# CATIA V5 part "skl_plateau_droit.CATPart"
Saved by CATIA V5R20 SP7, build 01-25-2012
Part number: skl_plateau_droit
Publications: "Point.F", "Point.G", "Droite.1", "Droite.2", "Droite.3"
Bounding box of the stored display mesh (mm): x 150 to 150, y 0 to 30, z 0 to 20
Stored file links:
  D:\IFMA\COURS\2A\projet balance IAO\catia\skl_plateau_droit.CATPart
  D:\IFMA\COURS\2A\projet balance IAO\catia\Skl_projet_balance.CATProduct
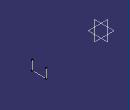
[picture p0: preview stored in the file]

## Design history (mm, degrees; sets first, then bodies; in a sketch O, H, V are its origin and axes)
Set1
  Point1 "Point.F": linked copy from another document
  Point2 "Point.G": linked copy from another document
  Plane1 "Plan_plateau_droit": linked copy from another document
Body1 (main body)
  Point3 "Point.F": stored without definition
  Point4 "Point.G": stored without definition
  Line1: type PtPt, FirstPoint Point1, SecondPoint Point2
  Line2: type PtDir, RefPoint Point1, Direction xy-plane, Start 0, End 20
  Line3: type PtDir, RefPoint Point2, Direction xy-plane, Start 0, End 20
